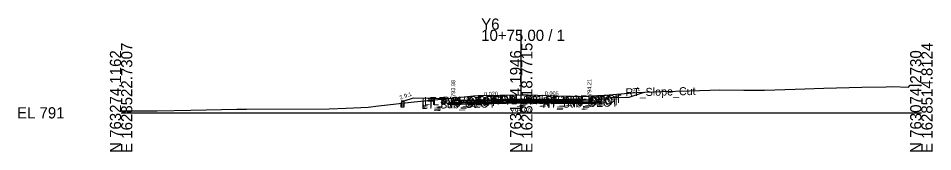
# Model space of a CAD drawing. Extents: x -26 to 203, y -10 to 6017.
# Drawn here: x -25.7 to 202.8, y 1490.3 to 1523.6 of the extents above; entities that cross this region are included whole.
import ezdxf

# ---------------------------------------------------------------- set-up
doc = ezdxf.new("R2010")
doc.units = 0
for name, color, linetype in [('Default', 7, 'Continuous'), ('Exist Cross Section Cell', 7, 'Continuous'), ('Exist XS Center Line Elevation Label', 7, 'Continuous'), ('Exist XS Ground Line', 7, 'Continuous'), ('Prop CMT Conc Surface', 7, 'Continuous'), ('Prop CMT Concrete Structures', 7, 'Continuous'), ('Prop CMT Pvmt Course 1', 7, 'Continuous'), ('Prop CMT Pvmt Course 1 CG', 7, 'Continuous'), ('Prop CMT Pvmt Course 2', 7, 'Continuous'), ('Prop CMT Pvmt Course 3', 7, 'Continuous'), ('Prop CMT Pvmt Surface', 7, 'Continuous'), ('Prop CMT Pvmt Surface Shoulder', 7, 'Continuous'), ('Prop CMT Pvmt Wedge Surface 1', 7, 'Continuous'), ('Prop CMT Pvmt Wedge Surface 2', 7, 'Continuous'), ('Prop CMT Pvmt Wedge Surface 3', 7, 'Continuous'), ('Prop CMT Shld Paved Course 1', 7, 'Continuous'), ('Prop CMT Shld Paved Course 2', 7, 'Continuous'), ('Prop CMT Shld Paved Course 3', 7, 'Continuous'), ('Prop CMT Slope Grass', 7, 'Continuous'), ('Prop CMT Subgrade Earthwork', 7, 'Continuous'), ('Prop XS Finish Grade CurbGutter', 7, 'Continuous'), ('Prop XS Hydro Elevations', 7, 'Continuous'), ('Prop XS SE Text', 7, 'Continuous'), ('Prop XS Side Slope Text', 7, 'Continuous'), ('Scratch_Level_0', 7, 'Continuous')]:
    doc.layers.add(name, color=color, linetype=linetype)

msp = doc.modelspace()

# ---------------------------------------------------------------- linework, layer by layer
at = {"layer": 'Exist Cross Section Cell'}
for p, q in [((100, 1500), (100, 1520.73)), ((0, 1500), (100, 1500)), ((100, 1500), (200, 1500))]:
    msp.add_line(p, q, dxfattribs=at)
at = {"layer": 'Exist XS Ground Line'}
msp.add_lwpolyline([(0, 1500.52), (8.99, 1500.52), (17.43, 1500.67), (28.96, 1500.88), (31.33, 1500.94), (52, 1501.02), (56.29, 1501.17), (61.76, 1501.42), (64.34, 1501.71), (73.23, 1502.76), (81.64, 1503.55), (86.59, 1504.06), (88.1, 1504.25), (89.23, 1504.28), (100, 1504.5), (100.37, 1504.51), (101.72, 1504.48), (111.23, 1504.18), (112.6, 1504.13), (115.54, 1504.03), (121.98, 1504.45), (128.75, 1505.06), (130.86, 1505.14), (135.18, 1505.32), (142.08, 1505.47), (149.65, 1505.72), (155.62, 1505.68), (160.81, 1505.66), (168.44, 1505.86), (175.61, 1506.16), (185.15, 1506.4), (191.2, 1506.51), (192.69, 1506.55), (196.83, 1506.41), (197.24, 1506.91), (200, 1506.91)], dxfattribs=at)
at = {"layer": 'Prop CMT Conc Surface'}
for points in [[(83, 1502.98), (83, 1503.48), (82.5, 1503.48)], [(85, 1503.08), (83, 1502.98)], [(115.01, 1503.27), (117.01, 1503.21)], [(117.01, 1503.21), (117.01, 1503.71), (117.51, 1503.71)]]:
    msp.add_lwpolyline(points, dxfattribs=at)
at = {"layer": 'Prop CMT Concrete Structures'}
for points in [[(85, 1503.08), (83, 1502.98), (83, 1503.48), (82.5, 1503.48)], [(82.5, 1503.48), (82.5, 1502.47), (85, 1502.5)], [(85, 1502.5), (85, 1503.08)], [(115.01, 1503.27), (117.01, 1503.21), (117.01, 1503.71), (117.51, 1503.71)], [(117.51, 1503.71), (117.51, 1502.71), (115.01, 1502.69)], [(115.01, 1502.69), (115.01, 1503.27)]]:
    msp.add_lwpolyline(points, dxfattribs=at)
at = {"layer": 'Prop CMT Pvmt Course 1'}
for points in [[(100, 1503.38), (85, 1503.08)], [(100, 1503.38), (85, 1503.08)], [(85, 1503.08), (85, 1502.83)], [(85, 1503.08), (85, 1502.83)], [(86.64, 1502.87), (100, 1503.13)], [(100, 1503.38), (88.61, 1503.16)], [(115.01, 1503.27), (100, 1503.38)], [(100, 1503.26), (100, 1503.38)], [(100, 1503.13), (100, 1503.38)], [(100, 1503.26), (100, 1503.38)], [(100, 1503.13), (100, 1503.38)], [(115.01, 1503.27), (100, 1503.38)], [(100, 1503.13), (115.01, 1503.02)], [(115.01, 1503.27), (115.01, 1503.02)]]:
    msp.add_lwpolyline(points, dxfattribs=at)
at = {"layer": 'Prop CMT Pvmt Course 1 CG'}
for points in [[(85, 1502.5), (82, 1502.46), (81.66, 1502.13)], [(81.66, 1502.13), (85, 1502.17)], [(85, 1502.17), (85, 1502.5)], [(115.01, 1502.69), (118.01, 1502.71), (118.34, 1502.38)], [(115.01, 1502.36), (115.01, 1502.69)], [(118.34, 1502.38), (115.01, 1502.36)]]:
    msp.add_lwpolyline(points, dxfattribs=at)
at = {"layer": 'Prop CMT Pvmt Course 2'}
for points in [[(100, 1503.13), (85, 1502.83)], [(85, 1502.83), (85, 1502.5)], [(85, 1502.83), (85, 1502.5)], [(86.64, 1502.53), (100, 1502.8)], [(100, 1502.8), (100, 1503.13)], [(100, 1502.8), (100, 1503.13)], [(115.01, 1503.02), (100, 1503.13)], [(100, 1502.8), (115.01, 1502.69)], [(115.01, 1503.02), (115.01, 1502.69)]]:
    msp.add_lwpolyline(points, dxfattribs=at)
at = {"layer": 'Prop CMT Pvmt Course 3'}
for points in [[(100, 1502.8), (85, 1502.5)], [(85, 1502.5), (85, 1502.17)], [(85, 1502.5), (85, 1502.17)], [(85, 1502.17), (100, 1502.47)], [(100, 1502.47), (100, 1502.8)], [(100, 1502.47), (100, 1502.8)], [(115.01, 1502.69), (100, 1502.8)], [(100, 1502.47), (115.01, 1502.36)], [(115.01, 1502.69), (115.01, 1502.36)]]:
    msp.add_lwpolyline(points, dxfattribs=at)
at = {"layer": 'Prop CMT Pvmt Surface'}
for points in [[(100, 1503.38), (85, 1503.08)], [(100, 1503.38), (88.61, 1503.16)], [(115.01, 1503.27), (100, 1503.38)]]:
    msp.add_lwpolyline(points, dxfattribs=at)
at = {"layer": 'Prop CMT Pvmt Surface Shoulder'}
msp.add_lwpolyline([(85, 1503.08), (85, 1503.08)], dxfattribs=at)
at = {"layer": 'Prop CMT Pvmt Wedge Surface 1'}
for points in [[(85, 1502.83), (85, 1503.08)], [(115.01, 1503.02), (100, 1503.13)], [(115.01, 1503.02), (115.01, 1503.27)]]:
    msp.add_lwpolyline(points, dxfattribs=at)
at = {"layer": 'Prop CMT Pvmt Wedge Surface 2'}
for points in [[(85, 1502.83), (85, 1503.08)], [(100, 1503.13), (88.61, 1502.91)], [(100, 1503.13), (100, 1503.38)], [(100, 1503.13), (100, 1503.38)], [(100, 1503.13), (100, 1503.38)], [(100, 1503.13), (100, 1503.38)], [(115.01, 1503.02), (115.01, 1503.27)]]:
    msp.add_lwpolyline(points, dxfattribs=at)
at = {"layer": 'Prop CMT Pvmt Wedge Surface 3'}
for points in [[(85, 1502.5), (85, 1503.08)], [(100, 1502.8), (88.61, 1502.57)], [(100, 1502.8), (100, 1503.38)], [(100, 1502.8), (100, 1503.38)], [(100, 1502.8), (100, 1503.38)], [(100, 1502.8), (100, 1503.38)], [(115.01, 1502.69), (115.01, 1503.27)]]:
    msp.add_lwpolyline(points, dxfattribs=at)
at = {"layer": 'Prop CMT Shld Paved Course 1'}
for points in [[(85, 1503.08), (85, 1503.08)], [(85, 1502.83), (85, 1503.08)]]:
    msp.add_lwpolyline(points, dxfattribs=at)
at = {"layer": 'Prop CMT Shld Paved Course 2'}
msp.add_lwpolyline([(85, 1502.5), (85, 1502.83)], dxfattribs=at)
at = {"layer": 'Prop CMT Shld Paved Course 3'}
msp.add_lwpolyline([(85, 1502.17), (85, 1502.5)], dxfattribs=at)
at = {"layer": 'Prop CMT Slope Grass'}
for p, q in [((73, 1503.67), (70.67, 1502.88)), ((82.5, 1503.48), (73, 1503.67))]:
    msp.add_line(p, q, dxfattribs=at)
for points in [[(117.51, 1503.71), (127.01, 1503.9), (130.71, 1505.13)], [(70.67, 1502.88), (70.67, 1501.38), (70, 1501.38), (70, 1502.38)]]:
    msp.add_lwpolyline(points, dxfattribs=at)
at = {"layer": 'Prop CMT Subgrade Earthwork'}
for points in [[(115.01, 1502.36), (118.34, 1502.38), (119.71, 1503.75)], [(85, 1502.17), (81.66, 1502.13), (80.26, 1503.52)], [(100, 1502.47), (85, 1502.17)], [(115.01, 1502.36), (100, 1502.47)]]:
    msp.add_lwpolyline(points, dxfattribs=at)
at = {"layer": 'Prop XS Finish Grade CurbGutter'}
for p, q in [((70.67, 1502.88), (70, 1502.88)), ((70, 1502.46), (70.35, 1502.83)), ((70, 1502.46), (70, 1501.88)), ((70, 1502.38), (70, 1502.38)), ((70, 1501.88), (70, 1501.38)), ((70.67, 1501.88), (70, 1501.88)), ((70.67, 1502.88), (70.47, 1502.88)), ((70.67, 1502.88), (70.67, 1501.88)), ((70.67, 1501.88), (70.67, 1501.38)), ((70.67, 1501.38), (70, 1501.38))]:
    msp.add_line(p, q, dxfattribs=at)
msp.add_arc((70.47, 1502.71), 0.166, 90, 136.0003, dxfattribs=at)

# ---------------------------------------------------------------- texts
at = {"layer": 'Default'}
msp.add_text('-', height=0.0001, dxfattribs=at).set_placement((0, 1500))
at = {"layer": 'Exist Cross Section Cell'}
for s, p in [('Y6', (90, 1520.73)), ('10+75.00 / 1', (90, 1517.93)), ('EL 791', (-26, 1498.6))]:
    msp.add_text(s, height=2.8, dxfattribs=at).set_placement(p)
for s, p in [('N 763274.1162', (0, 1490)), ('E 1628522.7307', (2.8, 1490)), ('N 763174.1946', (100, 1490)), ('E 1628518.7715', (102.8, 1490)), ('N 763074.2730', (200, 1490)), ('E 1628514.8124', (202.8, 1490))]:
    msp.add_text(s, height=2.8, rotation=90, dxfattribs=at).set_placement(p)
at = {"layer": 'Exist XS Center Line Elevation Label'}
msp.add_text('795.50', height=1.2, dxfattribs=at).set_placement((97.44, 1499.9))
at = {"layer": 'Prop XS Hydro Elevations'}
for s, p in [('793.98', (83.5, 1503.98)), ('794.21', (117.51, 1504.21))]:
    msp.add_text(s, height=1, rotation=90, dxfattribs=at).set_placement(p)
at = {"layer": 'Prop XS SE Text'}
for s, rotation, p in [('0.020', 1.1458, (90.73, 1504.2)), ('0.005', 359.7159, (105.9, 1504.36))]:
    msp.add_text(s, height=1, rotation=rotation, dxfattribs=at).set_placement(p)
at = {"layer": 'Prop XS Side Slope Text'}
for s, rotation, p in [('3:1', 18.4332, (127.95, 1505.01)), ('2.9:1', 18.7885, (69.8, 1503.29))]:
    msp.add_text(s, height=1, rotation=rotation, dxfattribs=at).set_placement(p)
at = {"layer": 'Scratch_Level_0'}
for s, p in [('RT_Slope_Cut', (126.06, 1504.1)), ('LT_PV2_OEOT', (75.2, 1501.64)), ('LT_PV1_OEOT', (75.76, 1501.9)), ('LT_PV1_OEEOP', (78, 1501.88)), ('PV2_PGL', (93.93, 1502.01)), ('PV1_PGL', (94.49, 1502.27)), ('RT_PV1_OEEOP', (101.09, 1502.06)), ('RT_PV2_OEOT', (105.4, 1501.86)), ('RT_PV3_OEOT', (105.4, 1501.53)), ('RT_PV1_OEOT', (105.97, 1502.12)), ('LT_Sub_OEOT', (75.1, 1500.97)), ('LT_PV3_OEOT', (75.2, 1501.31)), ('RT_Sub_OEOT', (105.31, 1501.19))]:
    msp.add_text(s, height=2, rotation=1.1458, dxfattribs=at).set_placement(p)

doc.saveas('drawing.dxf')
